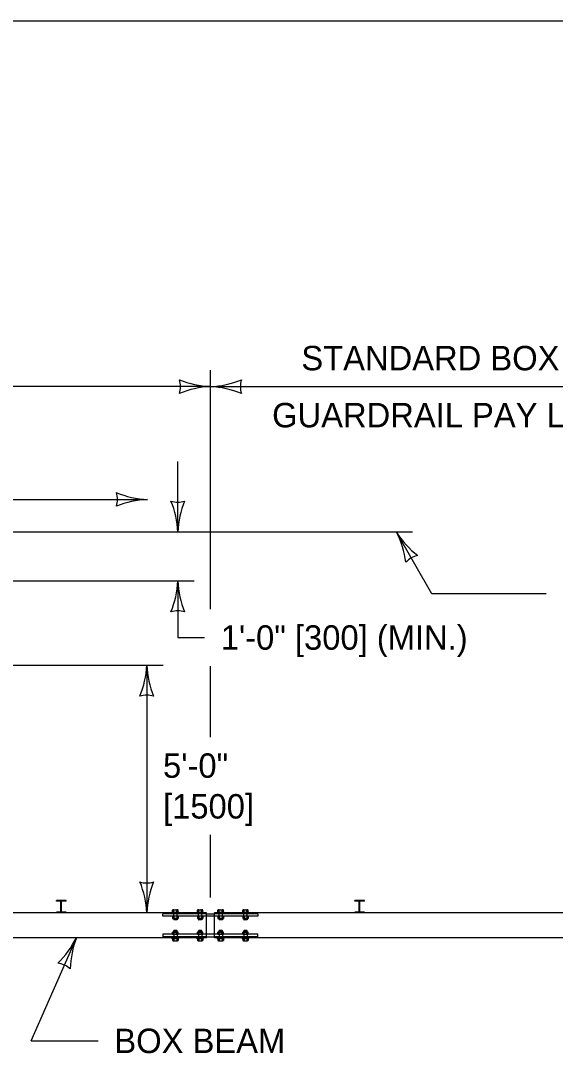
# Model space of a CAD drawing. Extents: x 49991.4 to 50021, y 49987.6 to 50011.4.
# Drawn here: x 50006.573 to 50007.884, y 49996.445 to 49998.999 of the extents above; entities that cross this region are included whole.
import ezdxf

# ---------------------------------------------------------------- set-up
doc = ezdxf.new("R2010")
doc.units = 0
for name, color, linetype in [('Level 1', 7, 'Continuous'), ('Level 2', 7, 'Continuous'), ('Level 3', 7, 'Continuous'), ('Level 4', 7, 'Continuous')]:
    doc.layers.add(name, color=color, linetype=linetype)

msp = doc.modelspace()

# ---------------------------------------------------------------- linework, layer by layer
at = {"layer": 'Level 1'}
for p, q in [((50006.6842, 49996.8397), (50006.6606, 49996.8397)), ((50006.6606, 49996.8381), (50006.6606, 49996.8397)), ((50006.6708, 49996.8381), (50006.6606, 49996.8381)), ((50006.6716, 49996.8116), (50006.6716, 49996.8373)), ((50006.6732, 49996.8116), (50006.6732, 49996.8373)), ((50006.6842, 49996.8381), (50006.674, 49996.8381)), ((50006.6842, 49996.8381), (50006.6842, 49996.8397)), ((50007.4162, 49996.8397), (50007.3926, 49996.8397)), ((50007.3926, 49996.8381), (50007.3926, 49996.8397)), ((50007.4028, 49996.8381), (50007.3926, 49996.8381)), ((50007.4036, 49996.8116), (50007.4036, 49996.8373)), ((50007.4052, 49996.8116), (50007.4052, 49996.8373)), ((50007.4162, 49996.8381), (50007.406, 49996.8381)), ((50007.4162, 49996.8381), (50007.4162, 49996.8397)), ((50007.0284, 49996.8092), (50004.8523, 49996.8092)), ((50006.6606, 49996.8092), (50006.6606, 49996.8108)), ((50006.6708, 49996.8108), (50006.6606, 49996.8108)), ((50006.6842, 49996.8108), (50006.674, 49996.8108)), ((50006.6842, 49996.8092), (50006.6842, 49996.8108)), ((50006.944, 49996.8112), (50006.9608, 49996.8112)), ((50006.944, 49996.8112), (50006.944, 49996.8092)), ((50006.9456, 49996.8115), (50006.9456, 49996.8164)), ((50006.9473, 49996.8167), (50006.9575, 49996.8167)), ((50006.949, 49996.8115), (50006.949, 49996.8164)), ((50006.9558, 49996.8115), (50006.9558, 49996.8164)), ((50006.9592, 49996.8115), (50006.9592, 49996.8164)), ((50006.9608, 49996.8112), (50006.9608, 49996.8092)), ((50007.0048, 49996.8112), (50007.0216, 49996.8112)), ((50007.0048, 49996.8112), (50007.0048, 49996.8092)), ((50007.0064, 49996.8115), (50007.0064, 49996.8164)), ((50007.0081, 49996.8167), (50007.0183, 49996.8167)), ((50007.0098, 49996.8115), (50007.0098, 49996.8164)), ((50007.0166, 49996.8115), (50007.0166, 49996.8164)), ((50007.02, 49996.8115), (50007.02, 49996.8164)), ((50007.0216, 49996.8112), (50007.0216, 49996.8092)), ((50007.0284, 49996.7484), (50007.0284, 49996.8092)), ((50007.0284, 49996.8073), (50007.0484, 49996.8073)), ((50007.0484, 49996.801), (50007.0284, 49996.801)), ((50008.33, 49996.8092), (50007.0484, 49996.8092)), ((50007.0484, 49996.7484), (50007.0484, 49996.8092)), ((50007.0552, 49996.8112), (50007.072, 49996.8112)), ((50007.0552, 49996.8112), (50007.0552, 49996.8092)), ((50007.0568, 49996.8115), (50007.0568, 49996.8164)), ((50007.0585, 49996.8167), (50007.0687, 49996.8167)), ((50007.0602, 49996.8115), (50007.0602, 49996.8164)), ((50007.067, 49996.8115), (50007.067, 49996.8164)), ((50007.0704, 49996.8115), (50007.0704, 49996.8164)), ((50007.072, 49996.8112), (50007.072, 49996.8092)), ((50007.116, 49996.8112), (50007.1328, 49996.8112)), ((50007.116, 49996.8112), (50007.116, 49996.8092)), ((50007.1176, 49996.8115), (50007.1176, 49996.8164)), ((50007.1193, 49996.8167), (50007.1295, 49996.8167)), ((50007.121, 49996.8115), (50007.121, 49996.8164)), ((50007.1278, 49996.8115), (50007.1278, 49996.8164)), ((50007.1312, 49996.8115), (50007.1312, 49996.8164)), ((50007.1328, 49996.8112), (50007.1328, 49996.8092)), ((50007.3926, 49996.8092), (50007.3926, 49996.8108)), ((50007.4028, 49996.8108), (50007.3926, 49996.8108)), ((50007.4162, 49996.8108), (50007.406, 49996.8108)), ((50007.4162, 49996.8092), (50007.4162, 49996.8108)), ((50007.0284, 49996.7484), (50004.8523, 49996.7484)), ((50006.944, 49996.7465), (50006.944, 49996.7484)), ((50006.9608, 49996.7465), (50006.9608, 49996.7484)), ((50007.0048, 49996.7465), (50007.0048, 49996.7484)), ((50007.0216, 49996.7465), (50007.0216, 49996.7484)), ((50007.0484, 49996.7567), (50007.0284, 49996.7567)), ((50007.0284, 49996.7504), (50007.0484, 49996.7504)), ((50008.3345, 49996.7484), (50007.0484, 49996.7484)), ((50007.0552, 49996.7465), (50007.0552, 49996.7484)), ((50007.072, 49996.7465), (50007.072, 49996.7484)), ((50007.116, 49996.7465), (50007.116, 49996.7484)), ((50007.1328, 49996.7465), (50007.1328, 49996.7484)), ((50006.944, 49996.7465), (50006.9608, 49996.7465)), ((50006.9456, 49996.7462), (50006.9456, 49996.7413)), ((50006.9473, 49996.741), (50006.9575, 49996.741)), ((50006.949, 49996.7462), (50006.949, 49996.7413)), ((50006.9558, 49996.7462), (50006.9558, 49996.7413)), ((50006.9592, 49996.7462), (50006.9592, 49996.7413)), ((50007.0048, 49996.7465), (50007.0216, 49996.7465)), ((50007.0064, 49996.7462), (50007.0064, 49996.7413)), ((50007.0081, 49996.741), (50007.0183, 49996.741)), ((50007.0098, 49996.7462), (50007.0098, 49996.7413)), ((50007.0166, 49996.7462), (50007.0166, 49996.7413)), ((50007.02, 49996.7462), (50007.02, 49996.7413)), ((50007.0552, 49996.7465), (50007.072, 49996.7465)), ((50007.0568, 49996.7462), (50007.0568, 49996.7413)), ((50007.0585, 49996.741), (50007.0687, 49996.741)), ((50007.0602, 49996.7462), (50007.0602, 49996.7413)), ((50007.067, 49996.7462), (50007.067, 49996.7413)), ((50007.0704, 49996.7462), (50007.0704, 49996.7413)), ((50007.116, 49996.7465), (50007.1328, 49996.7465)), ((50007.1176, 49996.7462), (50007.1176, 49996.7413)), ((50007.1193, 49996.741), (50007.1295, 49996.741)), ((50007.121, 49996.7462), (50007.121, 49996.7413)), ((50007.1278, 49996.7462), (50007.1278, 49996.7413)), ((50007.1312, 49996.7462), (50007.1312, 49996.7413))]:
    msp.add_line(p, q, dxfattribs=at)
msp.add_lwpolyline([(49999.3835, 49998.9992), (50016.7501, 49998.9992), (50016.7501, 49987.7988), (49999.3835, 49987.7988)], close=True, dxfattribs=at)
for centre, start, end in [((50006.6708, 49996.8373), 0, 90), ((50006.674, 49996.8373), 90, 180), ((50007.4028, 49996.8373), 0, 90), ((50007.406, 49996.8373), 90, 180), ((50006.6708, 49996.8116), 270, 0), ((50006.674, 49996.8116), 180, 270), ((50007.4028, 49996.8116), 270, 0), ((50007.406, 49996.8116), 180, 270)]:
    msp.add_arc(centre, 0.0008, start, end, dxfattribs=at)
for centre, major_axis, start_param, end_param in [((50006.9473, 49996.8146), (0.00339, 0), 1.056847, 2.094396), ((50006.9473, 49996.8133), (0.00339, 0), 4.188789, 5.226338), ((50006.9524, 49996.8082), (0.0135, 0), 1.315951, 1.825641), ((50006.9524, 49996.8197), (0.0135, 0), 4.457545, 4.967235), ((50006.9575, 49996.8146), (0.00339, 0), 1.047198, 2.084746), ((50006.9575, 49996.8133), (0.00339, 0), 4.198439, 5.235988), ((50007.0081, 49996.8146), (0.00339, 0), 1.056847, 2.094396), ((50007.0081, 49996.8133), (0.00339, 0), 4.188789, 5.226338), ((50007.0132, 49996.8082), (0.0135, 0), 1.315951, 1.825641), ((50007.0132, 49996.8197), (0.0135, 0), 4.457545, 4.967235), ((50007.0183, 49996.8146), (0.00339, 0), 1.047198, 2.084746), ((50007.0183, 49996.8133), (0.00339, 0), 4.198439, 5.235988), ((50007.0585, 49996.8146), (0.00339, 0), 1.056847, 2.094396), ((50007.0585, 49996.8133), (0.00339, 0), 4.188789, 5.226338), ((50007.0636, 49996.8082), (0.0135, 0), 1.315951, 1.825641), ((50007.0636, 49996.8197), (0.0135, 0), 4.457545, 4.967235), ((50007.0687, 49996.8146), (0.00339, 0), 1.047198, 2.084746), ((50007.0687, 49996.8133), (0.00339, 0), 4.198439, 5.235988), ((50007.1193, 49996.8146), (0.00339, 0), 1.056847, 2.094396), ((50007.1193, 49996.8133), (0.00339, 0), 4.188789, 5.226338), ((50007.1244, 49996.8082), (0.0135, 0), 1.315951, 1.825641), ((50007.1244, 49996.8197), (0.0135, 0), 4.457545, 4.967235), ((50007.1295, 49996.8146), (0.00339, 0), 1.047198, 2.084746), ((50007.1295, 49996.8133), (0.00339, 0), 4.198439, 5.235988), ((50006.9473, 49996.7443), (0.00339, 0), 1.056847, 2.094396), ((50006.9473, 49996.7431), (0.00339, 0), 4.188789, 5.226338), ((50006.9524, 49996.738), (0.0135, 0), 1.31595, 1.825641), ((50006.9524, 49996.7494), (0.0135, 0), 4.457545, 4.967234), ((50006.9575, 49996.7443), (0.00339, 0), 1.047198, 2.084746), ((50006.9575, 49996.7431), (0.00339, 0), 4.198439, 5.235988), ((50007.0081, 49996.7443), (0.00339, 0), 1.056847, 2.094396), ((50007.0081, 49996.7431), (0.00339, 0), 4.188789, 5.226338), ((50007.0132, 49996.738), (0.0135, 0), 1.31595, 1.825641), ((50007.0132, 49996.7494), (0.0135, 0), 4.457545, 4.967234), ((50007.0183, 49996.7443), (0.00339, 0), 1.047198, 2.084746), ((50007.0183, 49996.7431), (0.00339, 0), 4.198439, 5.235988), ((50007.0585, 49996.7443), (0.00339, 0), 1.056847, 2.094396), ((50007.0585, 49996.7431), (0.00339, 0), 4.188789, 5.226338), ((50007.0636, 49996.738), (0.0135, 0), 1.31595, 1.825641), ((50007.0636, 49996.7494), (0.0135, 0), 4.457545, 4.967234), ((50007.0687, 49996.7443), (0.00339, 0), 1.047198, 2.084746), ((50007.0687, 49996.7431), (0.00339, 0), 4.198439, 5.235988), ((50007.1193, 49996.7443), (0.00339, 0), 1.056847, 2.094396), ((50007.1193, 49996.7431), (0.00339, 0), 4.188789, 5.226338), ((50007.1244, 49996.738), (0.0135, 0), 1.31595, 1.825641), ((50007.1244, 49996.7494), (0.0135, 0), 4.457545, 4.967234), ((50007.1295, 49996.7443), (0.00339, 0), 1.047198, 2.084746), ((50007.1295, 49996.7431), (0.00339, 0), 4.198439, 5.235988)]:
    msp.add_ellipse(centre, major_axis=major_axis, ratio=0.623816, start_param=start_param, end_param=end_param, dxfattribs=at)
at = {"layer": 'Level 3'}
for p, q in [((50007.0384, 49997.5553), (50007.0384, 49998.1412)), ((50007.0384, 49998.1012), (50002.2804, 49998.1012)), ((50007.0384, 49998.1012), (50008.4895, 49998.1012)), ((50006.9584, 49997.7442), (50006.9584, 49997.9177)), ((50006.2837, 49997.8242), (50006.8837, 49997.8242)), ((50007.5344, 49997.7442), (50005.1367, 49997.7442)), ((50007.5814, 49997.5927), (50007.4944, 49997.7442)), ((50006.4678, 49997.6242), (50006.9984, 49997.6242)), ((50006.9584, 49997.6242), (50006.9584, 49997.4853)), ((50007.8619, 49997.5927), (50007.5814, 49997.5927)), ((50006.9584, 49997.4853), (50007.0237, 49997.4853)), ((50006.5163, 49997.4171), (50006.9222, 49997.4171)), ((50006.8822, 49997.4171), (50006.8822, 49996.8092)), ((50007.0384, 49997.2409), (50007.0384, 49997.4153)), ((50007.0384, 49996.8473), (50007.0384, 49997.0009)), ((50006.599, 49996.4952), (50006.7098, 49996.7484)), ((50006.599, 49996.4952), (50006.7628, 49996.4952))]:
    msp.add_line(p, q, dxfattribs=at)
for centre, radius, start, end in [((50006.9102, 49998.1012), 0.0548, 342.1388, 17.8612), ((50007.0499, 49998.3339), 0.233, 247.9228, 267.1727), ((50007.0292, 49998.3233), 0.2223, 272.3605, 292.544), ((50007.1666, 49998.1012), 0.0548, 162.1388, 197.8612), ((50007.0476, 49997.8791), 0.2223, 92.3605, 112.544), ((50007.0269, 49997.8685), 0.233, 67.9228, 87.1727), ((50006.8928, 49998.0464), 0.2223, 247.456, 267.6395), ((50006.7555, 49997.8242), 0.0548, 342.1388, 17.8612), ((50006.8952, 49997.5915), 0.233, 92.8273, 112.0772), ((50006.7363, 49997.7351), 0.2223, 2.3605, 22.544), ((50006.9584, 49997.8725), 0.0548, 252.1388, 287.8612), ((50007.1911, 49997.7327), 0.233, 157.9228, 177.1727), ((50007.2972, 49997.6416), 0.2223, 7.3075, 27.491), ((50007.6905, 49997.87), 0.233, 212.6788, 231.9286), ((50007.5582, 49997.633), 0.0548, 101.9903, 137.7126), ((50006.7257, 49997.6357), 0.233, 337.9228, 357.1727), ((50007.1805, 49997.6334), 0.2223, 182.3605, 202.544), ((50006.9584, 49997.496), 0.0548, 72.1388, 107.8612), ((50006.6495, 49997.4286), 0.233, 337.9228, 357.1727), ((50007.1044, 49997.4263), 0.2223, 182.3605, 202.544), ((50006.8822, 49997.2889), 0.0548, 72.1388, 107.8612), ((50006.6601, 49996.8001), 0.2223, 2.3605, 22.544), ((50006.8822, 49996.9375), 0.0548, 252.1388, 287.8612), ((50007.115, 49996.7978), 0.233, 157.9228, 177.1727), ((50006.5012, 49996.8523), 0.233, 314.2887, 333.5386), ((50006.917, 49996.6678), 0.2223, 158.7264, 178.9099), ((50006.6584, 49996.631), 0.0548, 48.5047, 84.2271)]:
    msp.add_arc(centre, radius, start, end, dxfattribs=at)
at = {"layer": 'Level 4'}
for p, q in [((50006.922, 49996.801), (50006.922, 49996.8073)), ((50007.0284, 49996.8073), (50006.922, 49996.8073)), ((50007.0284, 49996.801), (50006.922, 49996.801)), ((50006.942, 49996.8092), (50006.942, 49996.8073)), ((50006.9456, 49996.8007), (50006.9456, 49996.7958)), ((50006.9484, 49996.801), (50006.9484, 49996.8092)), ((50006.949, 49996.8007), (50006.949, 49996.7958)), ((50006.9558, 49996.8007), (50006.9558, 49996.7958)), ((50006.9564, 49996.801), (50006.9564, 49996.8092)), ((50006.9592, 49996.8007), (50006.9592, 49996.7958)), ((50006.9628, 49996.8092), (50006.9628, 49996.8073)), ((50007.0028, 49996.8092), (50007.0028, 49996.8073)), ((50007.0064, 49996.8007), (50007.0064, 49996.7958)), ((50007.0092, 49996.801), (50007.0092, 49996.8092)), ((50007.0098, 49996.8007), (50007.0098, 49996.7958)), ((50007.0166, 49996.8007), (50007.0166, 49996.7958)), ((50007.0172, 49996.801), (50007.0172, 49996.8092)), ((50007.02, 49996.8007), (50007.02, 49996.7958)), ((50007.0236, 49996.8092), (50007.0236, 49996.8073)), ((50007.1548, 49996.8073), (50007.0484, 49996.8073)), ((50007.1548, 49996.801), (50007.0484, 49996.801)), ((50007.0532, 49996.8092), (50007.0532, 49996.8073)), ((50007.0568, 49996.8007), (50007.0568, 49996.7958)), ((50007.0596, 49996.801), (50007.0596, 49996.8092)), ((50007.0602, 49996.8007), (50007.0602, 49996.7958)), ((50007.067, 49996.8007), (50007.067, 49996.7958)), ((50007.0676, 49996.801), (50007.0676, 49996.8092)), ((50007.0704, 49996.8007), (50007.0704, 49996.7958)), ((50007.074, 49996.8092), (50007.074, 49996.8073)), ((50007.114, 49996.8092), (50007.114, 49996.8073)), ((50007.1176, 49996.8007), (50007.1176, 49996.7958)), ((50007.1204, 49996.801), (50007.1204, 49996.8092)), ((50007.121, 49996.8007), (50007.121, 49996.7958)), ((50007.1278, 49996.8007), (50007.1278, 49996.7958)), ((50007.1284, 49996.801), (50007.1284, 49996.8092)), ((50007.1312, 49996.8007), (50007.1312, 49996.7958)), ((50007.1348, 49996.8092), (50007.1348, 49996.8073)), ((50007.1548, 49996.8073), (50007.1548, 49996.801)), ((50006.9473, 49996.7955), (50006.9575, 49996.7955)), ((50006.9484, 49996.7955), (50006.9484, 49996.7924)), ((50006.9484, 49996.7924), (50006.9488, 49996.792)), ((50006.956, 49996.7952), (50006.9488, 49996.7952)), ((50006.956, 49996.7944), (50006.9488, 49996.7944)), ((50006.956, 49996.7936), (50006.9488, 49996.7936)), ((50006.956, 49996.7928), (50006.9488, 49996.7928)), ((50006.956, 49996.792), (50006.9488, 49996.792)), ((50006.9564, 49996.7924), (50006.956, 49996.792)), ((50006.9564, 49996.7955), (50006.9564, 49996.7924)), ((50007.0081, 49996.7955), (50007.0183, 49996.7955)), ((50007.0092, 49996.7955), (50007.0092, 49996.7924)), ((50007.0092, 49996.7924), (50007.0096, 49996.792)), ((50007.0168, 49996.7952), (50007.0096, 49996.7952)), ((50007.0168, 49996.7944), (50007.0096, 49996.7944)), ((50007.0168, 49996.7936), (50007.0096, 49996.7936)), ((50007.0168, 49996.7928), (50007.0096, 49996.7928)), ((50007.0168, 49996.792), (50007.0096, 49996.792)), ((50007.0172, 49996.7924), (50007.0168, 49996.792)), ((50007.0172, 49996.7955), (50007.0172, 49996.7924)), ((50007.0585, 49996.7955), (50007.0687, 49996.7955)), ((50007.0596, 49996.7955), (50007.0596, 49996.7924)), ((50007.0596, 49996.7924), (50007.06, 49996.792)), ((50007.0672, 49996.7952), (50007.06, 49996.7952)), ((50007.0672, 49996.7944), (50007.06, 49996.7944)), ((50007.0672, 49996.7936), (50007.06, 49996.7936)), ((50007.0672, 49996.7928), (50007.06, 49996.7928)), ((50007.0672, 49996.792), (50007.06, 49996.792)), ((50007.0676, 49996.7924), (50007.0672, 49996.792)), ((50007.0676, 49996.7955), (50007.0676, 49996.7924)), ((50007.1193, 49996.7955), (50007.1295, 49996.7955)), ((50007.1204, 49996.7955), (50007.1204, 49996.7924)), ((50007.1204, 49996.7924), (50007.1208, 49996.792)), ((50007.128, 49996.7952), (50007.1208, 49996.7952)), ((50007.128, 49996.7944), (50007.1208, 49996.7944)), ((50007.128, 49996.7936), (50007.1208, 49996.7936)), ((50007.128, 49996.7928), (50007.1208, 49996.7928)), ((50007.128, 49996.792), (50007.1208, 49996.792)), ((50007.1284, 49996.7924), (50007.128, 49996.792)), ((50007.1284, 49996.7955), (50007.1284, 49996.7924)), ((50006.922, 49996.7567), (50006.922, 49996.7504)), ((50007.0284, 49996.7567), (50006.922, 49996.7567)), ((50007.0284, 49996.7504), (50006.922, 49996.7504)), ((50006.942, 49996.7484), (50006.942, 49996.7504)), ((50006.9456, 49996.757), (50006.9456, 49996.7619)), ((50006.9473, 49996.7622), (50006.9575, 49996.7622)), ((50006.9484, 49996.7653), (50006.9488, 49996.7657)), ((50006.9484, 49996.7622), (50006.9484, 49996.7653)), ((50006.9484, 49996.7567), (50006.9484, 49996.7484)), ((50006.956, 49996.7657), (50006.9488, 49996.7657)), ((50006.956, 49996.7649), (50006.9488, 49996.7649)), ((50006.956, 49996.7641), (50006.9488, 49996.7641)), ((50006.956, 49996.7633), (50006.9488, 49996.7633)), ((50006.956, 49996.7625), (50006.9488, 49996.7625)), ((50006.949, 49996.757), (50006.949, 49996.7619)), ((50006.9558, 49996.757), (50006.9558, 49996.7619)), ((50006.9564, 49996.7653), (50006.956, 49996.7657)), ((50006.9564, 49996.7622), (50006.9564, 49996.7653)), ((50006.9564, 49996.7567), (50006.9564, 49996.7484)), ((50006.9592, 49996.757), (50006.9592, 49996.7619)), ((50006.9628, 49996.7484), (50006.9628, 49996.7504)), ((50007.0028, 49996.7484), (50007.0028, 49996.7504)), ((50007.0064, 49996.757), (50007.0064, 49996.7619)), ((50007.0081, 49996.7622), (50007.0183, 49996.7622)), ((50007.0092, 49996.7653), (50007.0096, 49996.7657)), ((50007.0092, 49996.7622), (50007.0092, 49996.7653)), ((50007.0092, 49996.7567), (50007.0092, 49996.7484)), ((50007.0168, 49996.7657), (50007.0096, 49996.7657)), ((50007.0168, 49996.7649), (50007.0096, 49996.7649)), ((50007.0168, 49996.7641), (50007.0096, 49996.7641)), ((50007.0168, 49996.7633), (50007.0096, 49996.7633)), ((50007.0168, 49996.7625), (50007.0096, 49996.7625)), ((50007.0098, 49996.757), (50007.0098, 49996.7619)), ((50007.0166, 49996.757), (50007.0166, 49996.7619)), ((50007.0172, 49996.7653), (50007.0168, 49996.7657)), ((50007.0172, 49996.7622), (50007.0172, 49996.7653)), ((50007.0172, 49996.7567), (50007.0172, 49996.7484)), ((50007.02, 49996.757), (50007.02, 49996.7619)), ((50007.0236, 49996.7484), (50007.0236, 49996.7504)), ((50007.1548, 49996.7567), (50007.0484, 49996.7567)), ((50007.1548, 49996.7504), (50007.0484, 49996.7504)), ((50007.0532, 49996.7484), (50007.0532, 49996.7504)), ((50007.0568, 49996.757), (50007.0568, 49996.7619)), ((50007.0585, 49996.7622), (50007.0687, 49996.7622)), ((50007.0596, 49996.7653), (50007.06, 49996.7657)), ((50007.0596, 49996.7622), (50007.0596, 49996.7653)), ((50007.0596, 49996.7567), (50007.0596, 49996.7484)), ((50007.0672, 49996.7657), (50007.06, 49996.7657)), ((50007.0672, 49996.7649), (50007.06, 49996.7649)), ((50007.0672, 49996.7641), (50007.06, 49996.7641)), ((50007.0672, 49996.7633), (50007.06, 49996.7633)), ((50007.0672, 49996.7625), (50007.06, 49996.7625)), ((50007.0602, 49996.757), (50007.0602, 49996.7619)), ((50007.067, 49996.757), (50007.067, 49996.7619)), ((50007.0676, 49996.7653), (50007.0672, 49996.7657)), ((50007.0676, 49996.7622), (50007.0676, 49996.7653)), ((50007.0676, 49996.7567), (50007.0676, 49996.7484)), ((50007.0704, 49996.757), (50007.0704, 49996.7619)), ((50007.074, 49996.7484), (50007.074, 49996.7504)), ((50007.114, 49996.7484), (50007.114, 49996.7504)), ((50007.1176, 49996.757), (50007.1176, 49996.7619)), ((50007.1193, 49996.7622), (50007.1295, 49996.7622)), ((50007.1204, 49996.7653), (50007.1208, 49996.7657)), ((50007.1204, 49996.7622), (50007.1204, 49996.7653)), ((50007.1204, 49996.7567), (50007.1204, 49996.7484)), ((50007.128, 49996.7657), (50007.1208, 49996.7657)), ((50007.128, 49996.7649), (50007.1208, 49996.7649)), ((50007.128, 49996.7641), (50007.1208, 49996.7641)), ((50007.128, 49996.7633), (50007.1208, 49996.7633)), ((50007.128, 49996.7625), (50007.1208, 49996.7625)), ((50007.121, 49996.757), (50007.121, 49996.7619)), ((50007.1278, 49996.757), (50007.1278, 49996.7619)), ((50007.1284, 49996.7653), (50007.128, 49996.7657)), ((50007.1284, 49996.7622), (50007.1284, 49996.7653)), ((50007.1284, 49996.7567), (50007.1284, 49996.7484)), ((50007.1312, 49996.757), (50007.1312, 49996.7619)), ((50007.1348, 49996.7484), (50007.1348, 49996.7504)), ((50007.1548, 49996.7504), (50007.1548, 49996.7567))]:
    msp.add_line(p, q, dxfattribs=at)
for centre, major_axis, start_param, end_param in [((50006.9473, 49996.7989), (0.00339, 0), 1.056847, 2.094396), ((50006.9524, 49996.7925), (0.0135, 0), 1.31595, 1.825641), ((50006.9575, 49996.7989), (0.00339, 0), 1.047198, 2.084746), ((50007.0081, 49996.7989), (0.00339, 0), 1.056847, 2.094396), ((50007.0132, 49996.7925), (0.0135, 0), 1.31595, 1.825641), ((50007.0183, 49996.7989), (0.00339, 0), 1.047198, 2.084746), ((50007.0585, 49996.7989), (0.00339, 0), 1.056847, 2.094396), ((50007.0636, 49996.7925), (0.0135, 0), 1.31595, 1.825641), ((50007.0687, 49996.7989), (0.00339, 0), 1.047198, 2.084746), ((50007.1193, 49996.7989), (0.00339, 0), 1.056847, 2.094396), ((50007.1244, 49996.7925), (0.0135, 0), 1.31595, 1.825641), ((50007.1295, 49996.7989), (0.00339, 0), 1.047198, 2.084746), ((50006.9473, 49996.7976), (0.00339, 0), 4.188789, 5.226338), ((50006.9524, 49996.804), (0.0135, 0), 4.457545, 4.967234), ((50006.9575, 49996.7976), (0.00339, 0), 4.198439, 5.235988), ((50007.0081, 49996.7976), (0.00339, 0), 4.188789, 5.226338), ((50007.0132, 49996.804), (0.0135, 0), 4.457545, 4.967234), ((50007.0183, 49996.7976), (0.00339, 0), 4.198439, 5.235988), ((50007.0585, 49996.7976), (0.00339, 0), 4.188789, 5.226338), ((50007.0636, 49996.804), (0.0135, 0), 4.457545, 4.967234), ((50007.0687, 49996.7976), (0.00339, 0), 4.198439, 5.235988), ((50007.1193, 49996.7976), (0.00339, 0), 4.188789, 5.226338), ((50007.1244, 49996.804), (0.0135, 0), 4.457545, 4.967234), ((50007.1295, 49996.7976), (0.00339, 0), 4.198439, 5.235988), ((50006.9473, 49996.7601), (0.00339, 0), 1.056847, 2.094396), ((50006.9473, 49996.7588), (0.00339, 0), 4.188789, 5.226338), ((50006.9524, 49996.7537), (0.0135, 0), 1.315951, 1.825641), ((50006.9524, 49996.7652), (0.0135, 0), 4.457545, 4.967235), ((50006.9575, 49996.7601), (0.00339, 0), 1.047198, 2.084746), ((50006.9575, 49996.7588), (0.00339, 0), 4.198439, 5.235988), ((50007.0081, 49996.7601), (0.00339, 0), 1.056847, 2.094396), ((50007.0081, 49996.7588), (0.00339, 0), 4.188789, 5.226338), ((50007.0132, 49996.7537), (0.0135, 0), 1.315951, 1.825641), ((50007.0132, 49996.7652), (0.0135, 0), 4.457545, 4.967235), ((50007.0183, 49996.7601), (0.00339, 0), 1.047198, 2.084746), ((50007.0183, 49996.7588), (0.00339, 0), 4.198439, 5.235988), ((50007.0585, 49996.7601), (0.00339, 0), 1.056847, 2.094396), ((50007.0585, 49996.7588), (0.00339, 0), 4.188789, 5.226338), ((50007.0636, 49996.7537), (0.0135, 0), 1.315951, 1.825641), ((50007.0636, 49996.7652), (0.0135, 0), 4.457545, 4.967235), ((50007.0687, 49996.7601), (0.00339, 0), 1.047198, 2.084746), ((50007.0687, 49996.7588), (0.00339, 0), 4.198439, 5.235988), ((50007.1193, 49996.7601), (0.00339, 0), 1.056847, 2.094396), ((50007.1193, 49996.7588), (0.00339, 0), 4.188789, 5.226338), ((50007.1244, 49996.7537), (0.0135, 0), 1.315951, 1.825641), ((50007.1244, 49996.7652), (0.0135, 0), 4.457545, 4.967235), ((50007.1295, 49996.7601), (0.00339, 0), 1.047198, 2.084746), ((50007.1295, 49996.7588), (0.00339, 0), 4.198439, 5.235988)]:
    msp.add_ellipse(centre, major_axis=major_axis, ratio=0.623816, start_param=start_param, end_param=end_param, dxfattribs=at)

# ---------------------------------------------------------------- texts
at = {"layer": 'Level 2'}
for s, p in [('STANDARD BOX BEAM', (50007.2614, 49998.1412)), ('GUARDRAIL PAY LIMITS 1', (50007.1897, 49998.0012)), ('5\'-0"', (50006.9222, 49997.1409)), ('[1500]', (50006.9222, 49997.0409)), ('BOX BEAM', (50006.8028, 49996.4652))]:
    msp.add_text(s, height=0.06, dxfattribs=at).set_placement(p)
msp.add_text('1\'-0" [300] (MIN.)', height=0.06, rotation=360, dxfattribs=at).set_placement((50007.0637, 49997.4553))

doc.saveas('drawing.dxf')
